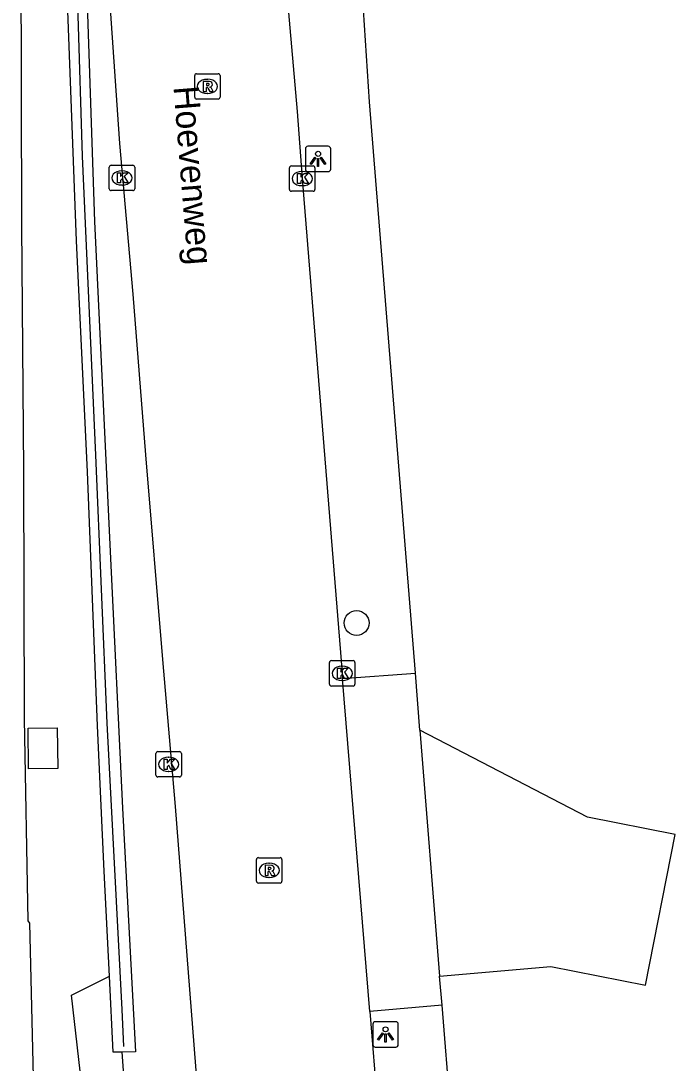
# Model space of a CAD drawing. Extents: x 157692 to 159670, y 381454 to 383289.
# Drawn here: x 157862.74 to 157888.49, y 382049.29 to 382090.3 of the extents above; entities that cross this region are included whole.
import ezdxf

# ---------------------------------------------------------------- set-up
doc = ezdxf.new("R2010")
doc.units = 0
for name, color, linetype in [('IMGEO_Berm_groen', 7, 'Continuous'), ('IMGEO_Boom', 7, 'Continuous'), ('IMGEO_Damwand', 7, 'Continuous'), ('IMGEO_Kolk', 7, 'Continuous'), ('IMGEO_Lichtpunt', 7, 'Continuous'), ('IMGEO_Muur', 7, 'Continuous'), ('IMGEO_Openbare_ruimte_label', 7, 'Continuous'), ('IMGEO_Rijbaan_autoweg', 7, 'Continuous'), ('IMGEO_Rijbaan_lokaal_open', 7, 'Continuous'), ('IMGEO_Rioolput', 7, 'Continuous'), ('IMGEO_Voetpad_open', 7, 'Continuous')]:
    doc.layers.add(name, color=color, linetype=linetype)

msp = doc.modelspace()

# ---------------------------------------------------------------- linework, layer by layer
at = {"layer": 'IMGEO_Berm_groen'}
for points in [[(157864.198, 382060.884), (157863.037, 382060.866), (157863.024, 382062.466), (157864.175, 382062.483), (157864.198, 382060.884)], [(157866.717, 382049.722), (157868.723, 382022.023), (157867.916, 382023.142), (157867.189, 382028.083), (157866.36, 382035.462), (157865.646, 382043.907), (157864.736, 382051.955), (157866.226, 382052.703)]]:
    msp.add_lwpolyline(points, dxfattribs=at)
at = {"layer": 'IMGEO_Boom'}
msp.add_circle((157875.955, 382066.608), 0.489, dxfattribs=at)
at = {"layer": 'IMGEO_Damwand'}
msp.add_lwpolyline([(157866.597, 382130.428), (157865.692, 382121.331), (157865.099, 382113.024), (157864.8, 382104.625), (157864.807, 382096.063), (157865.159, 382084.979), (157865.683, 382073.208), (157866.12, 382062.663), (157866.714, 382051.403), (157866.776, 382049.942)], dxfattribs=at)
at = {"layer": 'IMGEO_Kolk'}
for p, q in [((157866.221, 382083.697), (157866.221, 382084.549)), ((157866.296, 382084.623), (157867.148, 382084.623)), ((157866.709, 382084.403), (157866.734, 382084.403)), ((157867.222, 382084.549), (157867.222, 382083.697)), ((157873.314, 382083.671), (157873.314, 382084.523)), ((157873.389, 382084.597), (157874.241, 382084.597)), ((157873.802, 382084.377), (157873.827, 382084.377)), ((157874.315, 382084.523), (157874.315, 382083.671)), ((157866.732, 382083.843), (157866.707, 382083.843)), ((157867.148, 382083.623), (157866.296, 382083.623)), ((157874.241, 382083.597), (157873.389, 382083.597)), ((157873.825, 382083.817), (157873.8, 382083.817)), ((157874.888, 382064.201), (157874.888, 382065.053)), ((157874.963, 382065.127), (157875.815, 382065.127)), ((157875.889, 382065.053), (157875.889, 382064.201)), ((157875.376, 382064.907), (157875.401, 382064.907)), ((157875.399, 382064.347), (157875.374, 382064.347)), ((157875.815, 382064.127), (157874.963, 382064.127)), ((157868.057, 382060.621), (157868.057, 382061.473)), ((157868.132, 382061.547), (157868.984, 382061.547)), ((157868.545, 382061.327), (157868.57, 382061.327)), ((157869.058, 382061.473), (157869.058, 382060.621)), ((157868.984, 382060.547), (157868.132, 382060.547)), ((157868.568, 382060.767), (157868.543, 382060.767))]:
    msp.add_line(p, q, dxfattribs=at)
for points in [[(157866.221, 382083.697), (157866.221, 382084.549)], [(157866.296, 382084.623), (157867.148, 382084.623)], [(157866.542, 382084.323), (157866.665, 382084.323), (157866.665, 382084.172), (157866.795, 382084.323), (157866.959, 382084.323), (157866.813, 382084.172), (157866.966, 382083.923), (157866.814, 382083.923), (157866.729, 382084.087), (157866.665, 382084.02), (157866.665, 382083.923), (157866.542, 382083.923), (157866.542, 382084.323)], [(157867.222, 382084.549), (157867.222, 382083.697)], [(157873.314, 382083.671), (157873.314, 382084.523)], [(157873.389, 382084.597), (157874.241, 382084.597)], [(157873.635, 382084.297), (157873.758, 382084.297), (157873.758, 382084.146), (157873.888, 382084.297), (157874.052, 382084.297), (157873.906, 382084.146), (157874.059, 382083.897), (157873.907, 382083.897), (157873.822, 382084.061), (157873.758, 382083.994), (157873.758, 382083.897), (157873.635, 382083.897), (157873.635, 382084.297)], [(157874.315, 382084.523), (157874.315, 382083.671)], [(157867.148, 382083.623), (157866.296, 382083.623)], [(157874.241, 382083.597), (157873.389, 382083.597)], [(157874.888, 382064.201), (157874.888, 382065.053)], [(157874.963, 382065.127), (157875.815, 382065.127)], [(157875.889, 382065.053), (157875.889, 382064.201)], [(157875.209, 382064.827), (157875.332, 382064.827), (157875.332, 382064.676), (157875.462, 382064.827), (157875.626, 382064.827), (157875.48, 382064.676), (157875.633, 382064.427), (157875.481, 382064.427), (157875.396, 382064.591), (157875.332, 382064.524), (157875.332, 382064.427), (157875.209, 382064.427), (157875.209, 382064.827)], [(157875.815, 382064.127), (157874.963, 382064.127)], [(157868.057, 382060.621), (157868.057, 382061.473)], [(157868.132, 382061.547), (157868.984, 382061.547)], [(157869.058, 382061.473), (157869.058, 382060.621)], [(157868.378, 382061.247), (157868.501, 382061.247), (157868.501, 382061.096), (157868.631, 382061.247), (157868.795, 382061.247), (157868.649, 382061.096), (157868.802, 382060.847), (157868.65, 382060.847), (157868.565, 382061.011), (157868.501, 382060.944), (157868.501, 382060.847), (157868.378, 382060.847), (157868.378, 382061.247)], [(157868.984, 382060.547), (157868.132, 382060.547)]]:
    msp.add_lwpolyline(points, dxfattribs=at)
for centre, start, end in [((157866.298, 382084.547), 91.552, 178.448), ((157866.298, 382084.547), 91.552, 178.448), ((157867.146, 382084.547), 1.552, 88.448), ((157867.146, 382084.547), 1.552, 88.448), ((157873.391, 382084.521), 91.552, 178.448), ((157873.391, 382084.521), 91.552, 178.448), ((157874.239, 382084.521), 1.552, 88.448), ((157874.239, 382084.521), 1.552, 88.448), ((157866.298, 382083.699), 181.552, 268.448), ((157866.298, 382083.699), 181.552, 268.448), ((157867.146, 382083.699), 271.552, 358.448), ((157867.146, 382083.699), 271.552, 358.448), ((157873.391, 382083.673), 181.552, 268.448), ((157873.391, 382083.673), 181.552, 268.448), ((157874.239, 382083.673), 271.552, 358.448), ((157874.239, 382083.673), 271.552, 358.448), ((157874.965, 382065.051), 91.552, 178.448), ((157874.965, 382065.051), 91.552, 178.448), ((157875.813, 382065.051), 1.552, 88.448), ((157875.813, 382065.051), 1.552, 88.448), ((157874.965, 382064.203), 181.552, 268.448), ((157874.965, 382064.203), 181.552, 268.448), ((157875.813, 382064.203), 271.552, 358.448), ((157875.813, 382064.203), 271.552, 358.448), ((157868.134, 382061.471), 91.552, 178.448), ((157868.134, 382061.471), 91.552, 178.448), ((157868.982, 382061.471), 1.552, 88.448), ((157868.982, 382061.471), 1.552, 88.448), ((157868.134, 382060.623), 181.552, 268.448), ((157868.134, 382060.623), 181.552, 268.448), ((157868.982, 382060.623), 271.552, 358.448), ((157868.982, 382060.623), 271.552, 358.448)]:
    msp.add_arc(centre, 0.0765, start, end, dxfattribs=at)
for centre, major_axis, ratio, start_param, end_param in [((157866.708, 382084.123), (-0.387, 0.002), 0.722429, 4.712389, 7.853982), ((157866.733, 382084.123), (-0.39, 0.002), 0.717154, 1.570796, 4.712389), ((157873.801, 382084.097), (-0.387, 0.002), 0.722429, 4.712389, 7.853982), ((157873.826, 382084.097), (-0.39, 0.002), 0.717154, 1.570796, 4.712389), ((157875.375, 382064.627), (-0.387, 0.002), 0.722429, 4.712389, 7.853982), ((157875.4, 382064.627), (-0.39, 0.002), 0.717154, 1.570796, 4.712389), ((157868.544, 382061.047), (-0.387, 0.002), 0.722429, 4.712389, 7.853982), ((157868.569, 382061.047), (-0.39, 0.002), 0.717154, 1.570796, 4.712389)]:
    msp.add_ellipse(centre, major_axis=major_axis, ratio=ratio, start_param=start_param, end_param=end_param, dxfattribs=at)
at = {"layer": 'IMGEO_Lichtpunt'}
for p, q in [((157873.939, 382085.271), (157873.939, 382084.464)), ((157873.939, 382085.271), (157873.939, 382084.464)), ((157874.841, 382085.366), (157874.033, 382085.366)), ((157874.841, 382085.366), (157874.033, 382085.366)), ((157874.935, 382084.464), (157874.935, 382085.271)), ((157874.935, 382084.464), (157874.935, 382085.271)), ((157874.033, 382084.37), (157874.841, 382084.37)), ((157874.033, 382084.37), (157874.841, 382084.37)), ((157876.597, 382050.819), (157876.597, 382050.012)), ((157876.597, 382050.819), (157876.597, 382050.012)), ((157877.499, 382050.914), (157876.691, 382050.914)), ((157877.499, 382050.914), (157876.691, 382050.914)), ((157877.593, 382050.012), (157877.593, 382050.819)), ((157877.593, 382050.012), (157877.593, 382050.819)), ((157876.691, 382049.918), (157877.499, 382049.918)), ((157876.691, 382049.918), (157877.499, 382049.918))]:
    msp.add_line(p, q, dxfattribs=at)
for points in [[(157874.313, 382084.935), (157874.352, 382084.907), (157874.164, 382084.645), (157874.126, 382084.672), (157874.313, 382084.935)], [(157874.415, 382084.887), (157874.462, 382084.887), (157874.462, 382084.565), (157874.415, 382084.565), (157874.415, 382084.887)], [(157874.525, 382084.907), (157874.563, 382084.934), (157874.75, 382084.672), (157874.711, 382084.644), (157874.525, 382084.907)], [(157876.971, 382050.483), (157877.01, 382050.455), (157876.822, 382050.193), (157876.784, 382050.22), (157876.971, 382050.483)], [(157877.073, 382050.435), (157877.12, 382050.435), (157877.12, 382050.113), (157877.073, 382050.113), (157877.073, 382050.435)], [(157877.183, 382050.455), (157877.221, 382050.482), (157877.408, 382050.22), (157877.369, 382050.192), (157877.183, 382050.455)]]:
    msp.add_lwpolyline(points, dxfattribs=at)
for centre in [(157874.438, 382085.069), (157877.096, 382050.617)]:
    msp.add_circle(centre, 0.0994, dxfattribs=at)
for centre, start, end in [((157874.033, 382085.271), 90, 180), ((157874.033, 382085.271), 90, 180), ((157874.841, 382085.271), 0, 90), ((157874.841, 382085.271), 0, 90), ((157874.033, 382084.464), 180, 270), ((157874.033, 382084.464), 180, 270), ((157874.841, 382084.464), 270, 0), ((157874.841, 382084.464), 270, 360), ((157876.691, 382050.819), 90, 180), ((157876.691, 382050.819), 90, 180), ((157877.499, 382050.819), 0, 90), ((157877.499, 382050.819), 0, 90), ((157876.691, 382050.012), 180, 270), ((157876.691, 382050.012), 180, 270), ((157877.499, 382050.012), 270, 0), ((157877.499, 382050.012), 270, 360)]:
    msp.add_arc(centre, 0.0946, start, end, dxfattribs=at)
at = {"layer": 'IMGEO_Muur'}
for points in [[(157866.625, 382130.612), (157866.989, 382130.575), (157866.534, 382126.319), (157866.123, 382122.302), (157865.715, 382117.03), (157865.435, 382113.012), (157865.296, 382108.994), (157865.181, 382104.574), (157865.118, 382099.619), (157865.298, 382092.516), (157865.645, 382082.41), (157866.252, 382069.426), (157866.745, 382059.319), (157867.247, 382049.73), (157866.717, 382049.722)], [(157866.226, 382052.703), (157866.025, 382056.837), (157865.759, 382062.558), (157865.364, 382072.554), (157864.934, 382081.648), (157864.564, 382091.402), (157864.451, 382101.2), (157864.463, 382105.675), (157864.713, 382111.96), (157865.088, 382118.593), (157865.584, 382124.383), (157866.035, 382128.881)], [(157866.717, 382049.722), (157866.375, 382049.713), (157866.226, 382052.703)]]:
    msp.add_lwpolyline(points, dxfattribs=at)
at = {"layer": 'IMGEO_Rijbaan_autoweg'}
msp.add_lwpolyline([(157863.948, 382140.634), (157863.712, 382136.719), (157863.198, 382126.221), (157862.886, 382118.229), (157862.796, 382114.688), (157862.791, 382104.04), (157862.748, 382099.529), (157862.74, 382092.835), (157862.768, 382082.253), (157862.839, 382072.603), (157862.865, 382062.831), (157863.011, 382054.891), (157863.082, 382054.797), (157863.405, 382041.04), (157864.073, 382031.981), (157864.55, 382022.12), (157864.579, 382021.741), (157864.974, 382010.131), (157865.685, 381993.873), (157867.046, 381973.804), (157868.509, 381953.819)], dxfattribs=at)
at = {"layer": 'IMGEO_Rijbaan_lokaal_open'}
for points in [[(157871.576, 382023.267), (157870.986, 382031.847), (157870.47, 382038.411), (157869.622, 382049.165), (157868.821, 382059.387), (157868.329, 382065.166), (157867.661, 382073.221), (157867.158, 382079.552), (157866.641, 382085.477), (157866.108, 382093.059), (157865.914, 382095.666), (157865.775, 382100.358), (157865.866, 382105.246), (157866.047, 382108.426), (157866.439, 382112.482), (157867.045, 382117.03), (157868.022, 382122.573), (157869.408, 382129.429), (157871.426, 382139.303), (157873.582, 382149.701), (157875.281, 382157.955), (157876.98, 382166.191), (157877.081, 382166.673), (157877.157, 382167.036)], [(157876.358, 382128.915), (157874.961, 382122.317), (157874.175, 382117.687), (157873.026, 382108.688), (157872.785, 382104.713), (157872.707, 382100.949), (157872.794, 382096.181), (157873.613, 382086.739), (157873.815, 382084.097), (157875.389, 382064.627), (157875.406, 382064.42)], [(157876.471, 382051.324), (157875.406, 382064.42)], [(157878.448, 382062.387), (157879.225, 382052.703)], [(157879.225, 382052.703), (157883.605, 382053.086), (157887.326, 382052.352), (157888.494, 382058.282), (157885.047, 382058.968), (157878.448, 382062.387)], [(157876.471, 382051.324), (157877.38, 382040.147), (157878.096, 382030.891), (157879.093, 382016.501), (157879.267, 382014.333), (157880.461, 382000.889), (157880.48, 382000.654), (157881.168, 381991.916)]]:
    msp.add_lwpolyline(points, dxfattribs=at)
at = {"layer": 'IMGEO_Rioolput'}
for p, q in [((157869.583, 382087.296), (157869.583, 382088.148)), ((157869.658, 382088.222), (157870.51, 382088.222)), ((157870.071, 382088.002), (157870.096, 382088.002)), ((157870.584, 382088.148), (157870.584, 382087.296)), ((157870.51, 382087.222), (157869.658, 382087.222)), ((157870.094, 382087.442), (157870.069, 382087.442)), ((157872.015, 382056.446), (157872.015, 382057.298)), ((157872.09, 382057.372), (157872.942, 382057.372)), ((157873.016, 382057.298), (157873.016, 382056.446)), ((157872.503, 382057.152), (157872.528, 382057.152)), ((157872.942, 382056.372), (157872.09, 382056.372)), ((157872.526, 382056.592), (157872.501, 382056.592))]:
    msp.add_line(p, q, dxfattribs=at)
for points in [[(157869.583, 382087.296), (157869.583, 382088.148)], [(157869.658, 382088.222), (157870.51, 382088.222)], [(157870.172, 382087.92), (157869.92, 382087.922), (157869.92, 382087.522)], [(157870.584, 382088.148), (157870.584, 382087.296)], [(157869.92, 382087.522), (157870.044, 382087.522), (157870.044, 382087.684), (157870.055, 382087.684)], [(157870.098, 382087.841), (157870.044, 382087.841), (157870.044, 382087.76)], [(157870.044, 382087.76), (157870.096, 382087.76)], [(157870.102, 382087.655), (157870.173, 382087.522), (157870.313, 382087.522), (157870.248, 382087.648)], [(157870.51, 382087.222), (157869.658, 382087.222)], [(157872.015, 382056.446), (157872.015, 382057.298)], [(157872.09, 382057.372), (157872.942, 382057.372)], [(157873.016, 382057.298), (157873.016, 382056.446)], [(157872.604, 382057.07), (157872.352, 382057.072), (157872.352, 382056.672)], [(157872.352, 382056.672), (157872.476, 382056.672), (157872.476, 382056.834), (157872.487, 382056.834)], [(157872.53, 382056.991), (157872.476, 382056.991), (157872.476, 382056.91)], [(157872.476, 382056.91), (157872.528, 382056.91)], [(157872.534, 382056.805), (157872.605, 382056.672), (157872.745, 382056.672), (157872.68, 382056.798)], [(157872.942, 382056.372), (157872.09, 382056.372)]]:
    msp.add_lwpolyline(points, dxfattribs=at)
for centre, radius, start, end in [((157869.66, 382088.146), 0.0765, 91.552, 178.448), ((157869.66, 382088.146), 0.0765, 91.552, 178.448), ((157870.508, 382088.146), 0.0765, 1.552, 88.448), ((157870.508, 382088.146), 0.0765, 1.552, 88.448), ((157870.054, 382087.631), 0.0533, 26.0293, 88.6989), ((157870.08, 382087.949), 0.19, 274.7715, 282.9687), ((157870.104, 382087.745), 0.0964, 77.0061, 93.1865), ((157870.118, 382087.802), 0.0378, 276.6634, 79.6772), ((157870.171, 382087.81), 0.109, 350.3612, 89.416), ((157870.169, 382087.81), 0.112, 277.5842, 350.9817), ((157870.153, 382087.595), 0.108, 29.5134, 73.7905), ((157869.66, 382087.298), 0.0765, 181.552, 268.448), ((157869.66, 382087.298), 0.0765, 181.552, 268.448), ((157870.508, 382087.298), 0.0765, 271.552, 358.448), ((157870.508, 382087.298), 0.0765, 271.552, 358.448), ((157872.092, 382057.296), 0.0765, 91.552, 178.448), ((157872.092, 382057.296), 0.0765, 91.552, 178.448), ((157872.94, 382057.296), 0.0765, 1.552, 88.448), ((157872.94, 382057.296), 0.0765, 1.552, 88.448), ((157872.486, 382056.781), 0.0533, 26.0293, 88.6989), ((157872.512, 382057.099), 0.19, 274.7715, 282.9687), ((157872.536, 382056.895), 0.0964, 77.0061, 93.1865), ((157872.55, 382056.952), 0.0378, 276.6634, 79.6772), ((157872.603, 382056.96), 0.109, 350.3612, 89.416), ((157872.601, 382056.96), 0.112, 277.5842, 350.9817), ((157872.585, 382056.745), 0.108, 29.5134, 73.7905), ((157872.092, 382056.448), 0.0765, 181.552, 268.448), ((157872.092, 382056.448), 0.0765, 181.552, 268.448), ((157872.94, 382056.448), 0.0765, 271.552, 358.448), ((157872.94, 382056.448), 0.0765, 271.552, 358.448)]:
    msp.add_arc(centre, radius, start, end, dxfattribs=at)
for centre, major_axis, ratio, start_param, end_param in [((157870.07, 382087.722), (-0.387, 0.002), 0.722429, 4.712389, 7.853982), ((157870.095, 382087.722), (-0.39, 0.002), 0.717154, 1.570796, 4.712389), ((157872.502, 382056.872), (-0.387, 0.002), 0.722429, 4.712389, 7.853982), ((157872.527, 382056.872), (-0.39, 0.002), 0.717154, 1.570796, 4.712389)]:
    msp.add_ellipse(centre, major_axis=major_axis, ratio=ratio, start_param=start_param, end_param=end_param, dxfattribs=at)
at = {"layer": 'IMGEO_Voetpad_open'}
for points in [[(157878.268, 382064.633), (157876.464, 382087.116), (157875.755, 382097.986), (157875.768, 382105.479)], [(157875.406, 382064.42), (157878.268, 382064.633)], [(157878.448, 382062.387), (157878.268, 382064.633)], [(157879.317, 382051.562), (157879.225, 382052.703)], [(157879.317, 382051.562), (157876.471, 382051.324)], [(157884.473, 381992.148), (157882.495, 382012.836), (157880.959, 382031.099), (157879.317, 382051.562)]]:
    msp.add_lwpolyline(points, dxfattribs=at)

# ---------------------------------------------------------------- texts
at = {"layer": 'IMGEO_Openbare_ruimte_label'}
msp.add_text('Hoevenweg', height=1, rotation=274.5876, dxfattribs=at).set_placement((157868.746, 382087.708))

doc.saveas('drawing.dxf')
